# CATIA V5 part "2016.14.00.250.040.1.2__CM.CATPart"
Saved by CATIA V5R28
Part number: 2016.14.00.250.040.1.2__CM
Property "id_number": "2016.14.00.250.040.1.2"
Publications: "Absolute Axis System", "driver", "slider", "base", "cam diagram"
Bounding box of the stored display mesh (mm): x -40 to 210, y -180 to 180, z 0 to 310
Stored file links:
  N:\B2\Normteile\K\2016\11-14\025\cm\2016.14.00.250.040.1.2__CM.CATPart
  H:\CAD_Startmodelle\Tests\fill-in_PRT-SL_TEMPLATE.xlsx
  H:\CAD_Startmodelle\V5-R24\R24_TEMPLATE_PRT_FIBRO_CAM_TECNOLOGIES_INDEX.xlsx
  H:\z_Einordnen\170511__Anfrage_TK_HN\170511__CC01_TKHN.CATPart
  N:\B2\Normteile\K\2016\9xxx\2016.9024.1705.001\Entwurf_\170511__CC01_TKHN.CATPart
  N:\B2\Normteile\K\2016\9xxx\2016.9024.1707.006\Konstruktion\2016.9024.1707.006__HP__CUSTOMIZED_CAM_CM.CATPart
  N:\B2\Normteile\K\2016\9xxx\2016.9024.1707.005\Konstruktion\2016.9024.1707.005__HP__CUSTOMIZED_CAM_CM.CATPart
  N:\B2\Normteile\K\2016\9xxx\2016.9024.1707.008\Konstruktion\2016.9024.1707.008__HP__CUSTOMIZED_CAM_CM.CATPart
  N:\B2\Normteile\K\2016\9xxx\2016.9024.1707.009\Konstruktion\2016.9024.1707.009__HP__CUSTOMIZED_CAM_CM.CATPart
  N:\B2\Normteile\K\2016\9xxx\2016.9024.1707.010\Konstruktion\2016.9024.1707.010__HP__CUSTOMIZED_CAM_CM.CATPart
  N:\B2\Normteile\K\2016\9xxx\2016.9024.1708.002\Konstruktion\2016.9024.1708.002__HP__CUSTOMIZED_CAM_CM.CATPart
  N:\B2\Normteile\K\2016\9xxx\2016.9024.1802.001\Konstruktion\2016.9024.1802.001__HP__CUSTOMIZED_CAM_CM.CATPart
  N:\B2\Normteile\K\2016\9xxx\2016.9024.1802.002\Konstruktion\2016.9024.1802.002__HP__CUSTOMIZED_CAM_CM.CATPart
  N:\B2\Normteile\K\2016\9xxx\2016.9024.1811.003\Konstruktion\2016.9024.1811.003__HP__CUSTOMIZED_CAM_CM.CATPart
  N:\B2\Normteile\K\2016\9xxx\2016.9015.1811.001\Konstruktion\am\2016.9015.1811.001__AM__FCC_HV_DMC_0125-00.CATPart
  N:\B2\Normteile\K\2016\9xxx\2016.9024.1811.009\Konstruktion\2016.9024.1811.009__HP__CUSTOMIZED_CAM_CM.CATPart
  N:\B2\Normteile\K\2016\9xxx\2016.9024.1911.002\Konstruktion\am\2016.9024.1911.002__AM__CUSTOMIZED_CAM_CM.CATPart
  N:\B2\Normteile\K\2016\9xxx\2016.9024.2002.006\Konstruktion\2016.9024.2002.006__AM.CATPart
  N:\B2\Normteile\K\2016\9xxx\2016.9024.2004.001\Konstruktion\2016.9024.2004.001__AM__FCC_HV_CAEC_0260-45.CATPart
  N:\B2\Normteile\K\2016\9xxx\2016.9024.2006.002\Konstruktion\2016.9024.2006.002__AM__FCC_HV_CAEC_0260-40.CATPart
  N:\B2\Normteile\K\2016\9xxx\2016.9024.2006.005\Konstruktion\am\2016.9024.2006.005__AM__CFCC_HV_AEPC_0080-65.CATPart
  N:\B2\Normteile\K\2016\9xxx\2016.9024.2006.004\Konstruktion\am\2016.9024.2006.004__AM__CFCC_HV_AEC_0210-35.CATPart
  N:\B2\Normteile\K\2016\9xxx\2016.9026.2006.001\Konstruktion\am\2016.9026.2006.001__AM__FCC_LV_CAEC_0180-40.CATPart
  N:\B2\Normteile\K\2016\9xxx\2016.9015.2007.001\Konstruktion\am\2016.9015.2007.001__AM__FCC_HV_CDMPC_0090-00.CATPart
  N:\B2\Normteile\K\2016\9xxx\2016.9024.2005.001\Konstruktion\am\2016.9024.2005.001__AM__CFCC_HV_AEPC_1400-70.CATPart
  N:\B2\Normteile\K\2016\9xxx\2016.9024.2007.004\Konstruktion\am\2016.9024.2007.004__AM__CFCC_HV_AEC_1250-80.CATPart
  N:\B2\Normteile\K\2016\11-14\005\2016.11.00.052.040.1.02__AS__DIE_MOUNT_CAM__W52_A0_S40.CATProduct
  N:\B2\Normteile\K\2016\11-14\015\2016.11.00.150.060.1.02__AS__DIE_MOUNT_CAM__W150_A0_S60.CATProduct
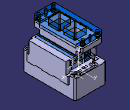
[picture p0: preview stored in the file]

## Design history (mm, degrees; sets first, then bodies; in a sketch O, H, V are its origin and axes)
Parameters
  group "process_parameters"
    modeltype = ""
    stocklist = ""
    id_number = "2016.14.00.250.040.1.2"
    id_number_rough_part = ""
    revision_index = ""
    revision_date = ""
    revision_description = ""
    category = ""
    material = ""
    manufacturing_information = ""
    standard = ""
  group "release_parameters_startmodel"
    sm_revision_index = "2016_00" {design table}
    sm_revision_date = "20.08.2016" {design table}
    sm_revision_name = "Meyer" {design table}
    sm_revision_description = "new part template FIBRO cam tecnologies" {design table}
AxisSystem1: origin (0, 0, 0), X (1, 0, 0), Y (0, 1, 0), Z (0, 0, 1)
Set1 "reference elements"
  Sketch1 "cam diagram" on ZX plane of AxisSystem1, origin (0, 0, 0), H (-1, 0, 0), V (0, 0, 1)
    line L1 (0, 0) -> (40, 0)
    line L2 (40, 0) -> (0, 40)
    point P2 (0, 40)
    line L3 (0, 40) -> (0, 0)
    length L1 = 40
    angle H L2 = 45
    horizontal: L1 H
    coincidence: P2 V
    vertical: L3 V
Body1 "finished_part" (main body)
  Body2 "rough_part"
  Add1 "rough_part": tool Body2
  Body3 "milling operations"
  Remove1 "milling operations": tool Body3
  Body4 "drilling operations"
  Remove2 "drilling operations": tool Body4
Body5 "driver"
  Solid1: solid without history
Body6 "slider"
  Solid2: solid without history
Body7 "base"
  Solid3: solid without history
Body8 "opened position"
  Body9 "slider"
    Body10 "slider"
      Solid4: linked copy from another document
    Assemble1: tool Body10
    Translate1: FirstPoint vertex [element of Sketch1 | element of Sketch1], SecondPoint vertex [element of Sketch1 | element of Sketch1], ToTransfor Assemble1
  Assemble2: tool Body9
  Body11 "driver"
    Body12 "driver"
      Solid5: linked copy from another document
    Assemble3: tool Body12
    Translate2: FirstPoint vertex [element of Sketch1 | element of Sketch1], SecondPoint vertex [element of Sketch1 | element of Sketch1], ToTransfor Assemble3
  Assemble4: tool Body11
